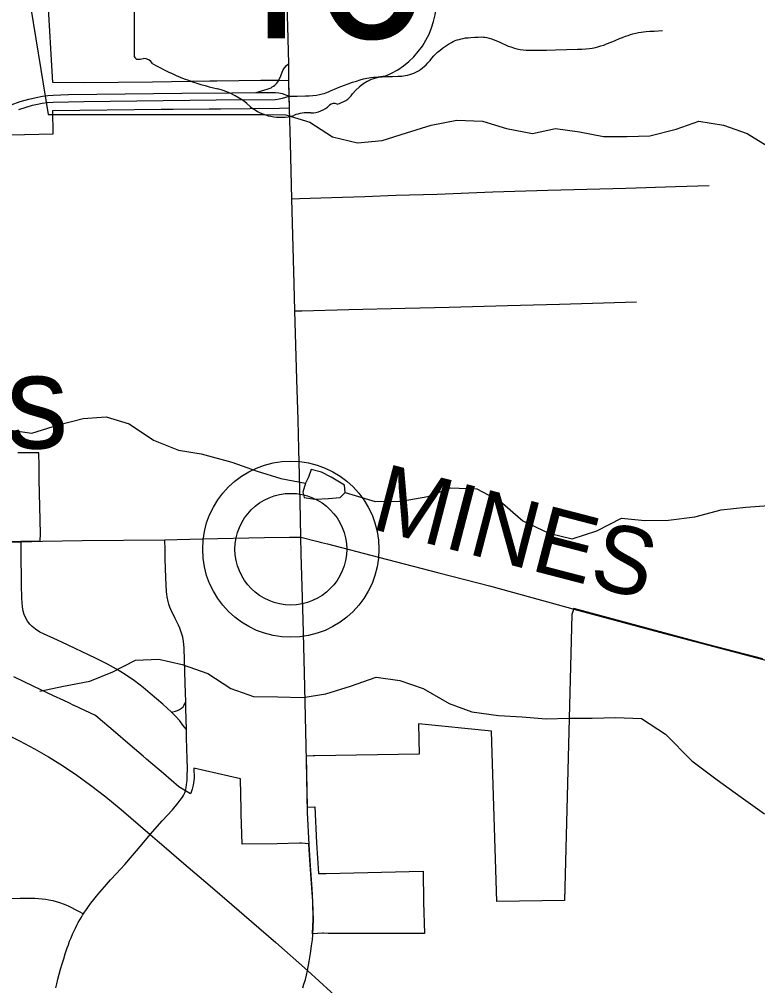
# Model space of a CAD drawing. Extents: x -6.4 to 34, y -4.2 to 22.
# Drawn here: x 5.307 to 5.93, y 16.015 to 16.831 of the extents above; entities that cross this region are included whole.
import ezdxf

# ---------------------------------------------------------------- set-up
doc = ezdxf.new("R2010")
doc.units = 0
for name, color, linetype in [('GM_X_City_Street', 7, 'Continuous'), ('GM_X_Corporation', 7, 'Continuous'), ('GM_X_County_Road', 7, 'Continuous'), ('GM_X_County_Road_Text', 7, 'Continuous'), ('GM_X_Minor_Lake', 7, 'Continuous'), ('GM_X_Minor_River', 7, 'Continuous'), ('GM_X_State_Route', 7, 'Continuous'), ('GM_X_State_Shield', 7, 'Continuous'), ('GM_X_Township_Road', 7, 'Continuous'), ('GM_X_Unincorporated', 7, 'Continuous'), ('GM_X_Unincorporated_Location', 7, 'Continuous'), ('GM_X_Unincorporated_Text', 7, 'Continuous'), ('GM_X_US_Route', 7, 'Continuous')]:
    doc.layers.add(name, color=color, linetype=linetype)

msp = doc.modelspace()

# ---------------------------------------------------------------- linework, layer by layer
at = {"layer": 'GM_X_City_Street'}
for points in [[(5.50647, 16.7697), (5.51289, 16.77146), (5.5167, 16.77275), (5.51899, 16.77363), (5.52006, 16.77424), (5.52109, 16.77489), (5.52209, 16.77565), (5.52294, 16.7765), (5.524, 16.77759), (5.52478, 16.7787), (5.52524, 16.77954), (5.52726, 16.78377), (5.52837, 16.7868), (5.52918, 16.78862), (5.53042, 16.79042), (5.53218, 16.79231), (5.53394, 16.79418)], [(5.29949, 16.75926), (5.30719, 16.76186), (5.31464, 16.76396), (5.32063, 16.76539), (5.32599, 16.76637), (5.33052, 16.76696), (5.335, 16.76735), (5.34792, 16.76777), (5.4437, 16.76903), (5.48598, 16.76933), (5.50647, 16.7697), (5.52289, 16.76959), (5.52568, 16.76917), (5.52848, 16.76859), (5.53444, 16.76653)], [(5.30611, 16.75528), (5.31238, 16.75724), (5.31762, 16.7588), (5.32176, 16.75983), (5.3258, 16.76057), (5.33008, 16.76111), (5.33509, 16.76149), (5.36094, 16.76199), (5.47261, 16.7633), (5.52286, 16.76376), (5.52601, 16.76416), (5.52864, 16.76473), (5.53444, 16.76653)], [(5.33744, 16.01316), (5.33818, 16.01669), (5.33909, 16.02047), (5.34016, 16.02467), (5.3414, 16.02911), (5.34271, 16.03346), (5.34404, 16.03783), (5.34527, 16.04193), (5.3461, 16.04457), (5.34692, 16.04687), (5.34791, 16.04966), (5.34898, 16.05254), (5.35013, 16.05542), (5.35153, 16.05862), (5.35277, 16.06134), (5.35384, 16.06356), (5.35507, 16.06607), (5.35631, 16.06849), (5.35752, 16.07073), (5.35895, 16.07301), (5.3599, 16.07459), (5.36068, 16.07579), (5.36166, 16.07721), (5.3632, 16.07953), (5.36487, 16.08197), (5.36693, 16.08468), (5.3694, 16.08789), (5.3717, 16.09065), (5.3745, 16.09405), (5.37838, 16.09866), (5.38348, 16.10433), (5.38842, 16.10976), (5.39547, 16.11752), (5.41029, 16.13449), (5.41709, 16.14285)], [(5.29757, 16.0887), (5.30727, 16.08894), (5.31237, 16.08903), (5.31558, 16.08901), (5.31961, 16.08893), (5.32257, 16.08877), (5.32586, 16.08844), (5.3289, 16.08802), (5.33155, 16.08759), (5.33482, 16.08695), (5.33756, 16.08628), (5.3405, 16.08538), (5.34354, 16.08431), (5.34584, 16.0834), (5.34839, 16.08225), (5.35053, 16.08118), (5.35316, 16.07978), (5.35645, 16.07805), (5.36068, 16.07579)]]:
    msp.add_lwpolyline(points, dxfattribs=at)
at = {"layer": 'GM_X_Corporation'}
for points in [[(5.29866, 16.73373), (5.33519, 16.73464), (5.3347, 16.75437), (5.42618, 16.75536), (5.43643, 16.75547), (5.46675, 16.75579), (5.47634, 16.7559), (5.52602, 16.75643), (5.53455, 16.75652), (5.53393, 16.77946), (5.52461, 16.77984), (5.52081, 16.77979), (5.51053, 16.77965), (5.51026, 16.77965), (5.47319, 16.77915), (5.46723, 16.77907), (5.41892, 16.77843), (5.36093, 16.77765), (5.33466, 16.77792), (5.3333, 16.80195), (5.32921, 16.87476)], [(5.26277, 16.38974), (5.30775, 16.39055), (5.32412, 16.39095), (5.32449, 16.39686), (5.32339, 16.44251), (5.32312, 16.45387), (5.32285, 16.46524), (5.30534, 16.46508)], [(5.9342, 16.2911), (5.88737, 16.30339), (5.8509, 16.31317), (5.77457, 16.33353), (5.77296, 16.32867), (5.7667, 16.08696), (5.70974, 16.08628), (5.70563, 16.21146), (5.70502, 16.22997), (5.6435, 16.23618), (5.64411, 16.21059), (5.5559, 16.20926), (5.5547, 16.20923), (5.54867, 16.2088), (5.54963, 16.16579), (5.55608, 16.16613), (5.5573, 16.13583), (5.5592, 16.10969), (5.56035, 16.10972), (5.56546, 16.10984), (5.64742, 16.11176), (5.64784, 16.08555), (5.6486, 16.0592), (5.62742, 16.05921), (5.56732, 16.05925), (5.56333, 16.05926), (5.56255, 16.05926), (5.55412, 16.05885), (5.55439, 16.06524), (5.55454, 16.07103), (5.55422, 16.08636), (5.55353, 16.0975), (5.55178, 16.12116), (5.55095, 16.13486), (5.54476, 16.13532), (5.54381, 16.1353), (5.54309, 16.13529), (5.52421, 16.135), (5.49455, 16.13454), (5.49392, 16.16025), (5.49384, 16.16352), (5.4932, 16.18969), (5.45383, 16.1989), (5.45398, 16.19042), (5.45329, 16.1845), (5.45243, 16.18102), (5.45155, 16.17841), (5.4509, 16.17698), (5.44115, 16.18314), (5.42821, 16.1942), (5.41396, 16.20638), (5.41103, 16.20888), (5.40001, 16.2183), (5.38561, 16.23062), (5.37318, 16.24124), (5.37089, 16.2432), (5.35282, 16.25173), (5.35261, 16.25183), (5.34827, 16.25388), (5.34398, 16.2559), (5.3354, 16.25995), (5.31888, 16.26775), (5.30173, 16.27584)]]:
    msp.add_lwpolyline(points, dxfattribs=at)
at = {"layer": 'GM_X_County_Road'}
for p, q in [((5.26297, 16.38919), (5.30795, 16.38999)), ((5.30795, 16.38999), (5.32601, 16.39043))]:
    msp.add_line(p, q, dxfattribs=at)
for points in [[(5.32601, 16.39043), (5.35967, 16.39104), (5.42944, 16.3918), (5.46086, 16.39254), (5.51355, 16.3936), (5.53458, 16.39388), (5.54421, 16.394), (5.55744, 16.39044), (5.56174, 16.38953), (5.56669, 16.38824), (5.60966, 16.37697), (5.66074, 16.36385), (5.7034, 16.35269), (5.75547, 16.33833), (5.77373, 16.33326)], [(5.77373, 16.33326), (5.77477, 16.33298), (5.8511, 16.31261), (5.88757, 16.30284), (5.9344, 16.29055), (5.98622, 16.27632)]]:
    msp.add_lwpolyline(points, dxfattribs=at)
at = {"layer": 'GM_X_Minor_Lake'}
msp.add_line((5.54821, 16.43965), (5.54589, 16.43206), dxfattribs=at)
msp.add_lwpolyline([(5.54589, 16.43206), (5.54699, 16.4275), (5.55607, 16.42594), (5.56743, 16.42665), (5.57728, 16.42736), (5.58147, 16.43152), (5.58114, 16.43798), (5.56982, 16.44448), (5.56151, 16.4487), (5.55282, 16.45102), (5.55051, 16.44458), (5.54821, 16.43965)], dxfattribs=at)
at = {"layer": 'GM_X_Minor_River'}
for points in [[(5.31201, 16.86694), (5.33096, 16.75099), (5.51232, 16.7509), (5.53163, 16.7508), (5.55165, 16.74463), (5.57088, 16.73201), (5.59205, 16.72697), (5.61289, 16.72915), (5.63338, 16.73551), (5.65424, 16.74187), (5.67585, 16.74632), (5.69743, 16.74546), (5.71783, 16.73929), (5.73976, 16.73501), (5.7591, 16.73909), (5.77953, 16.73634), (5.79957, 16.73244), (5.81964, 16.73235), (5.83895, 16.73302), (5.86094, 16.73861), (5.8803, 16.74536), (5.9011, 16.74184), (5.92112, 16.73491), (5.94149, 16.72228)], [(5.29747, 16.48451), (5.31714, 16.48176), (5.33952, 16.48887), (5.36038, 16.49409), (5.3797, 16.49552), (5.39935, 16.48973), (5.41971, 16.47596), (5.44086, 16.4675), (5.46015, 16.46437), (5.48585, 16.45742), (5.50738, 16.44972), (5.52741, 16.44355), (5.54821, 16.43965)], [(5.58147, 16.43152), (5.6068, 16.42418), (5.62875, 16.42446), (5.6515, 16.42815), (5.67047, 16.43565), (5.69281, 16.43479), (5.71243, 16.42444), (5.73164, 16.40764), (5.75353, 16.39728), (5.77319, 16.39263), (5.79405, 16.39937), (5.81494, 16.4099), (5.83462, 16.40791), (5.85469, 16.4082), (5.87667, 16.41113), (5.89904, 16.4171), (5.91988, 16.41928), (5.9392, 16.42071)], [(5.32371, 16.26372), (5.34381, 16.26818), (5.36617, 16.27225), (5.38553, 16.28014), (5.40452, 16.28992), (5.42422, 16.29097), (5.44388, 16.28632), (5.46579, 16.27862), (5.48502, 16.26599), (5.50429, 16.25945), (5.52473, 16.25897), (5.54593, 16.25849), (5.56525, 16.26144), (5.58612, 16.26818), (5.60775, 16.27567), (5.6278, 16.27291), (5.64744, 16.26599), (5.66932, 16.25335), (5.68859, 16.24642), (5.71091, 16.24328), (5.73097, 16.24204), (5.7514, 16.24043), (5.77072, 16.2411), (5.79003, 16.24101), (5.80972, 16.24167), (5.83167, 16.24081), (5.85203, 16.22742), (5.87423, 16.20491), (5.89571, 16.18886), (5.91606, 16.17433), (5.93566, 16.16018)]]:
    msp.add_lwpolyline(points, dxfattribs=at)
at = {"layer": 'GM_X_State_Route'}
for p, q in [((5.54991, 16.16145), (5.54894, 16.20484)), ((5.55115, 16.13431), (5.54991, 16.16145))]:
    msp.add_line(p, q, dxfattribs=at)
for points in [[(5.53413, 16.77891), (5.53413, 16.78432), (5.53394, 16.79418), (5.53328, 16.82533), (5.53239, 16.85276)], [(5.53474, 16.75602), (5.53444, 16.76653), (5.53412, 16.7774), (5.53413, 16.77891)], [(5.54178, 16.49317), (5.54086, 16.5272), (5.53919, 16.58505), (5.53853, 16.60783), (5.53643, 16.67981), (5.53539, 16.72665), (5.53474, 16.75602)], [(5.54894, 16.20484), (5.54808, 16.24257), (5.54726, 16.27921), (5.54602, 16.32397), (5.54453, 16.3799), (5.54421, 16.394), (5.54353, 16.42403), (5.54245, 16.46816), (5.54178, 16.49317)], [(5.55432, 16.0583), (5.55459, 16.06468), (5.55474, 16.07047), (5.55442, 16.08581), (5.55373, 16.09695), (5.55198, 16.1206), (5.55115, 16.13431)], [(5.54972, 16.02775), (5.55118, 16.03559), (5.55237, 16.04229), (5.55327, 16.04866), (5.55394, 16.05378), (5.55432, 16.0583)], [(5.54577, 16.0131), (5.54683, 16.01623), (5.54799, 16.02025), (5.54889, 16.02396), (5.54972, 16.02775)]]:
    msp.add_lwpolyline(points, dxfattribs=at)
at = {"layer": 'GM_X_State_Shield'}
msp.add_line((5.40341, 17.00138), (5.40341, 16.80126), dxfattribs=at)
for centre, radius, start, end in [((5.58881, 16.84797), 0.06994, 292.30889, 8.98584), ((5.40645, 16.80082), 0.00308, 171.95839, 258.30661), ((5.40692, 16.82129), 0.02352, 267.33899, 280.60386), ((5.41173, 16.78971), 0.00848, 29.74838, 93.27175), ((5.51879, 16.96951), 0.20192, 240.41292, 257.1985), ((5.6183, 16.74507), 0.0383, 94.40312, 142.57675), ((5.45859, 16.71135), 0.06318, 47.18416, 75.83597), ((5.56977, 16.78186), 0.0226, 282.87319, 323.27711), ((5.57234, 16.75435), 0.00601, 65.75173, 132.64842), ((5.52692, 16.78872), 0.04009, 230.70037, 286.29184), ((5.55009, 16.71953), 0.03294, 85.69512, 111.20995), ((5.55301, 16.77373), 0.02136, 268.77702, 315.54927)]:
    msp.add_arc(centre, radius, start, end, dxfattribs=at)
at = {"layer": 'GM_X_Township_Road'}
for points in [[(5.69376, 16.81645), (5.69654, 16.8165), (5.69836, 16.81638), (5.6995, 16.81625), (5.70107, 16.816), (5.70328, 16.81551), (5.70509, 16.81502), (5.70731, 16.8142), (5.70937, 16.81329), (5.7115, 16.8123), (5.71432, 16.81103), (5.71701, 16.80982), (5.71931, 16.80884), (5.72154, 16.80801), (5.72442, 16.80703), (5.72655, 16.80645), (5.72926, 16.80587), (5.7319, 16.80554), (5.73445, 16.80537), (5.73757, 16.80529), (5.74366, 16.80529), (5.75155, 16.80545), (5.7592, 16.8056), (5.77779, 16.80614), (5.78133, 16.80625), (5.78478, 16.80649), (5.78799, 16.80682), (5.79013, 16.80714), (5.79292, 16.80763), (5.7949, 16.80813), (5.79737, 16.80887), (5.79992, 16.80969), (5.8023, 16.81059), (5.80608, 16.81215), (5.80962, 16.81363), (5.8131, 16.81505), (5.81571, 16.81609), (5.81826, 16.81708), (5.82041, 16.81786), (5.82254, 16.81864), (5.82451, 16.81921), (5.82698, 16.81979), (5.82928, 16.82019), (5.8316, 16.82056), (5.83348, 16.82077), (5.83577, 16.82104), (5.83874, 16.82126), (5.84246, 16.82151), (5.8496, 16.82199)], [(5.53444, 16.76653), (5.54098, 16.76661), (5.54797, 16.7667), (5.55117, 16.76686), (5.55422, 16.7671), (5.55726, 16.76743), (5.55989, 16.76784), (5.56211, 16.76833), (5.56375, 16.76882), (5.5654, 16.7694), (5.56749, 16.77023), (5.56976, 16.77112), (5.57248, 16.77227), (5.5752, 16.7734), (5.57807, 16.77457), (5.58109, 16.77573), (5.58416, 16.77687), (5.58786, 16.77818), (5.59107, 16.77925), (5.59436, 16.78032), (5.59715, 16.78106), (5.59987, 16.78163), (5.60316, 16.7822), (5.60546, 16.78245), (5.60754, 16.78262), (5.60941, 16.78269), (5.61278, 16.78285), (5.61706, 16.78302), (5.62159, 16.78318), (5.62619, 16.78334), (5.6294, 16.7835), (5.63219, 16.78383), (5.63417, 16.78416), (5.63606, 16.78465), (5.63778, 16.78522), (5.63943, 16.78588), (5.64133, 16.78678), (5.64351, 16.788), (5.64519, 16.78909), (5.64692, 16.79032), (5.6484, 16.79155), (5.64996, 16.79303), (5.65145, 16.79459), (5.65326, 16.79673), (5.6549, 16.7987), (5.65647, 16.80043), (5.6582, 16.80232), (5.65968, 16.80371), (5.6614, 16.80519), (5.66371, 16.807), (5.66536, 16.80823), (5.66708, 16.80938), (5.66873, 16.81045), (5.67128, 16.81193), (5.67276, 16.81267), (5.6745, 16.8134), (5.67605, 16.81399), (5.67778, 16.81448), (5.67942, 16.81489), (5.68131, 16.8153), (5.68321, 16.81562), (5.68534, 16.81587), (5.6876, 16.81612), (5.69094, 16.81636), (5.69376, 16.81645)], [(5.53643, 16.67981), (5.543, 16.68002), (5.57009, 16.68088), (5.59814, 16.68184), (5.62446, 16.68273), (5.65925, 16.68377), (5.70621, 16.68555), (5.75276, 16.687), (5.81848, 16.68885), (5.8605, 16.69021), (5.88879, 16.69102)], [(5.53919, 16.58505), (5.5449, 16.5852), (5.58462, 16.58624), (5.63232, 16.58727), (5.66933, 16.58824), (5.7186, 16.58968), (5.76244, 16.59088), (5.8275, 16.59273)], [(5.4476, 16.23132), (5.44464, 16.23517), (5.4419, 16.23872), (5.43865, 16.24257), (5.43505, 16.24616), (5.42764, 16.25271), (5.42221, 16.25732), (5.41688, 16.26185), (5.41105, 16.2668), (5.40363, 16.2725), (5.39594, 16.27782), (5.38856, 16.28248), (5.38091, 16.2867), (5.37583, 16.28919), (5.37085, 16.29164), (5.34228, 16.30521), (5.33567, 16.30823), (5.3299, 16.31087), (5.32383, 16.31381), (5.32026, 16.31608), (5.31744, 16.31835), (5.31536, 16.32049), (5.31354, 16.32287), (5.31171, 16.32597), (5.3105, 16.3287), (5.30963, 16.33154), (5.30906, 16.33513), (5.30879, 16.33846), (5.30848, 16.34248), (5.30831, 16.35361), (5.30802, 16.38218), (5.30795, 16.38999)], [(5.4464, 16.17893), (5.44722, 16.18206), (5.44772, 16.18502), (5.44813, 16.18831), (5.4483, 16.19217), (5.44839, 16.19818), (5.44814, 16.20706), (5.44799, 16.21528), (5.44775, 16.22449), (5.4476, 16.23132), (5.4473, 16.24009), (5.44707, 16.24959), (5.44696, 16.25461), (5.44656, 16.27058), (5.44633, 16.28052), (5.44573, 16.30026), (5.44547, 16.30318), (5.44524, 16.30576), (5.44454, 16.30933), (5.44377, 16.31186), (5.44294, 16.31457), (5.44193, 16.31704), (5.44085, 16.31969), (5.43947, 16.32253), (5.43815, 16.32523), (5.43717, 16.32717), (5.4356, 16.33027), (5.43455, 16.33279), (5.43366, 16.33492), (5.43286, 16.33738), (5.4321, 16.33971), (5.43125, 16.34342), (5.43101, 16.34582), (5.43079, 16.34783), (5.4303, 16.35961), (5.42955, 16.37575), (5.4295, 16.38323), (5.42944, 16.3918)], [(5.43505, 16.24616), (5.4383, 16.24704), (5.44012, 16.24754), (5.44185, 16.24831), (5.44343, 16.24935), (5.44473, 16.2507), (5.44535, 16.2518), (5.44696, 16.25461)], [(5.41709, 16.14285), (5.42722, 16.15436), (5.43578, 16.16372), (5.44055, 16.16939), (5.44318, 16.17285), (5.44425, 16.17433), (5.44508, 16.17581), (5.44582, 16.17745), (5.4464, 16.17893)]]:
    msp.add_lwpolyline(points, dxfattribs=at)
at = {"layer": 'GM_X_Unincorporated'}
for radius in [0.0744, 0.04716]:
    msp.add_circle((5.53572, 16.38377), radius, dxfattribs=at)
at = {"layer": 'GM_X_Unincorporated_Location'}
msp.add_line((5.53572, 16.38377), (5.53572, 16.38377), dxfattribs=at)
at = {"layer": 'GM_X_US_Route'}
for points in [[(5.28915, 16.23048), (5.30654, 16.22194), (5.31928, 16.21521), (5.33126, 16.20834), (5.34298, 16.20105), (5.35496, 16.19301), (5.36664, 16.18456), (5.37953, 16.17461), (5.39259, 16.16391), (5.41709, 16.14285), (5.42876, 16.1325), (5.4454, 16.11832), (5.46752, 16.09948), (5.486, 16.08373), (5.50263, 16.06927), (5.52306, 16.0515), (5.54972, 16.02775)], [(5.54972, 16.02775), (5.56945, 16.0098), (5.58995, 15.99148), (5.63207, 15.95375), (5.65211, 15.93603), (5.66225, 15.92687), (5.70974, 15.88487), (5.71865, 15.87703), (5.72418, 15.87217), (5.75832, 15.84224), (5.78678, 15.81724), (5.84396, 15.76746), (5.89398, 15.72372), (5.96292, 15.66386)]]:
    msp.add_lwpolyline(points, dxfattribs=at)

# ---------------------------------------------------------------- texts
at = {"layer": 'GM_X_County_Road_Text'}
msp.add_text('MINES', height=0.056818, rotation=345.43358, dxfattribs=at).set_placement((5.602, 16.40139))
at = {"layer": 'GM_X_State_Shield'}
msp.add_text('46', height=0.131836, dxfattribs=at).set_placement((5.45493, 16.81537))
at = {"layer": 'GM_X_Unincorporated_Text'}
msp.add_text('Madden Corners', height=0.0789773, rotation=0.00001, dxfattribs=at).set_placement((4.56125, 16.46891))

doc.saveas('drawing.dxf')
